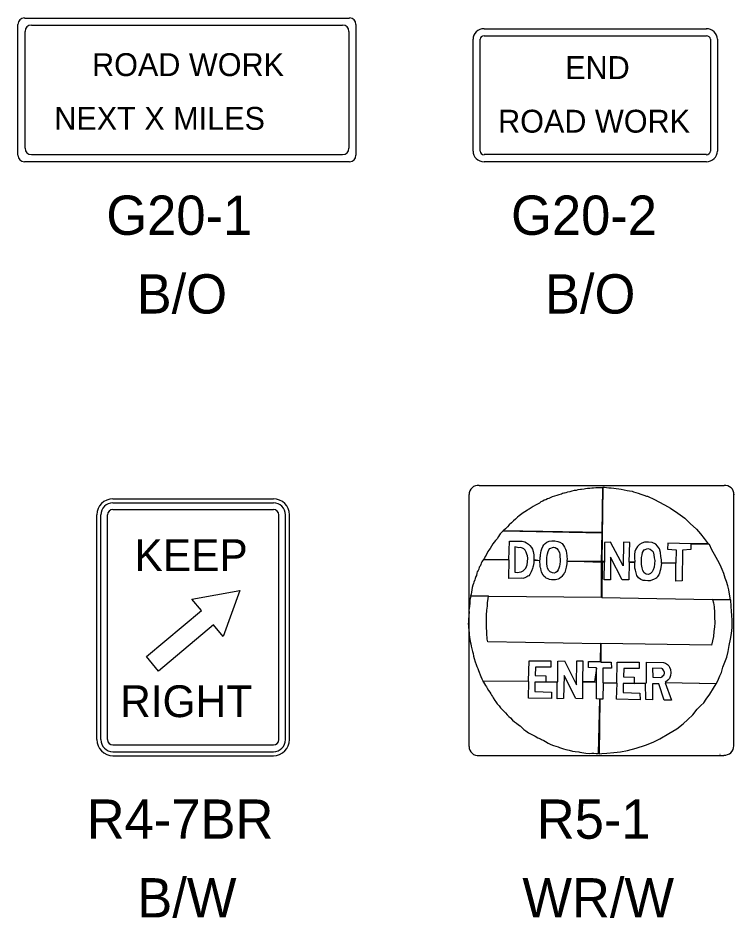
# Model space of a CAD drawing. Extents: x 10034 to 10794, y 10044 to 10499.
# Drawn here: x 10107 to 10170.8, y 10408.8 to 10488.9 of the extents above; entities that cross this region are included whole.
import ezdxf

# ---------------------------------------------------------------- set-up
doc = ezdxf.new("R2010")
doc.units = 0
for name, color, linetype in [('DSDate', 7, 'Continuous'), ('DSIndex', 7, 'Continuous'), ('DSText', 7, 'Continuous'), ('PlotBorder_dp', 7, 'Continuous')]:
    doc.layers.add(name, color=color, linetype=linetype)

msp = doc.modelspace()

# ---------------------------------------------------------------- linework, layer by layer
at = {"layer": 'DSDate'}
for p, q in [((10108.184, 10488.322), (10135.926, 10488.322)), ((10107.618, 10477.339), (10107.618, 10487.756)), ((10136.492, 10487.756), (10136.492, 10477.339)), ((10148.186, 10477.091), (10148.186, 10487.048)), ((10148.544, 10487.367), (10168.351, 10487.367)), ((10168.71, 10487.048), (10168.71, 10477.091)), ((10135.926, 10476.772), (10108.184, 10476.772)), ((10168.351, 10476.773), (10148.544, 10476.773))]:
    msp.add_line(p, q, dxfattribs=at)
for centre, start, end in [((10108.183, 10487.757), 90, 180), ((10135.924, 10487.757), 0, 90), ((10108.183, 10477.339), 180, 270), ((10135.924, 10477.339), 270, 0)]:
    msp.add_arc(centre, 0.566, start, end, dxfattribs=at)
for centre, major_axis, start_param, end_param in [((10148.543, 10487.049), (-0.359, 0), 4.712389, 6.283185), ((10168.35, 10487.049), (-0.359, 0), 3.141593, 4.712389), ((10148.543, 10477.091), (-0.359, 0), 0, 1.570796), ((10168.35, 10477.091), (0.359, 0), 4.712389, 6.283185)]:
    msp.add_ellipse(centre, major_axis=major_axis, ratio=0.888888, start_param=start_param, end_param=end_param, dxfattribs=at)
at = {"layer": 'DSIndex'}
for p, q in [((10148.104, 10447.307), (10169.927, 10447.307)), ((10147.212, 10424.055), (10147.212, 10446.487)), ((10170.801, 10424.11), (10170.801, 10446.578)), ((10115.457, 10446.119), (10129.76, 10446.119)), ((10115.457, 10445.761), (10129.76, 10445.761)), ((10114.025, 10424.662), (10114.025, 10444.689)), ((10114.382, 10424.662), (10114.382, 10444.689)), ((10114.98, 10424.662), (10114.98, 10444.689)), ((10115.457, 10445.166), (10129.76, 10445.166)), ((10130.238, 10424.662), (10130.238, 10444.689)), ((10130.832, 10424.662), (10130.832, 10444.689)), ((10131.191, 10424.662), (10131.191, 10444.689)), ((10115.457, 10424.185), (10129.76, 10424.185)), ((10115.457, 10423.589), (10129.76, 10423.589)), ((10115.457, 10423.23), (10129.76, 10423.23)), ((10148.104, 10423.235), (10169.908, 10423.235))]:
    msp.add_line(p, q, dxfattribs=at)
for points in [[(10159.069, 10443.097), (10159.126, 10447.137), (10159.079, 10447.096), (10158.97, 10447.09), (10158.831, 10447.096), (10158.634, 10447.092), (10158.492, 10447.082), (10158.282, 10447.067), (10158.153, 10447.063), (10157.965, 10447.04), (10157.863, 10447.022), (10157.759, 10447.022), (10157.574, 10447.006), (10157.451, 10446.98), (10157.231, 10446.946), (10157.134, 10446.938), (10156.925, 10446.911), (10156.908, 10446.912), (10156.755, 10446.867), (10156.556, 10446.844), (10156.361, 10446.798), (10156.176, 10446.751), (10155.968, 10446.695), (10155.816, 10446.661), (10155.702, 10446.628), (10155.638, 10446.612), (10155.522, 10446.58), (10155.44, 10446.527), (10155.191, 10446.46), (10155.018, 10446.418), (10154.816, 10446.348), (10154.619, 10446.277), (10154.316, 10446.141), (10154.204, 10446.11), (10154.034, 10446.025), (10153.9, 10445.982), (10153.767, 10445.914), (10153.61, 10445.837), (10153.483, 10445.739), (10153.294, 10445.644), (10153.11, 10445.547), (10152.919, 10445.427), (10152.722, 10445.312), (10152.547, 10445.192), (10152.47, 10445.161), (10152.4, 10445.108), (10152.185, 10444.958), (10152.029, 10444.854), (10151.892, 10444.772), (10151.662, 10444.59), (10151.505, 10444.49), (10151.352, 10444.309), (10151.159, 10444.163), (10151.131, 10444.129), (10150.984, 10443.971), (10150.784, 10443.792), (10150.62, 10443.612), (10150.434, 10443.43), (10150.251, 10443.274)], [(10159.154, 10447.151), (10159.265, 10447.151), (10159.447, 10447.126), (10159.665, 10447.096), (10159.858, 10447.087), (10160.093, 10447.063), (10160.309, 10447.043), (10160.563, 10447.015), (10160.773, 10446.974), (10161.027, 10446.915), (10161.284, 10446.868), (10161.494, 10446.813), (10161.742, 10446.783), (10161.858, 10446.728), (10162.064, 10446.687), (10162.288, 10446.608), (10162.517, 10446.539), (10162.775, 10446.45), (10163.016, 10446.345), (10163.096, 10446.337), (10163.743, 10446.049), (10164.127, 10445.852), (10164.614, 10445.58), (10165.15, 10445.28), (10165.823, 10444.834), (10166.419, 10444.393), (10166.913, 10443.921), (10167.476, 10443.396), (10167.827, 10442.999), (10168.143, 10442.588), (10168.518, 10442.095), (10167.003, 10442.097), (10164.913, 10442.153), (10164.895, 10441.621), (10165.657, 10441.564), (10165.644, 10440.383), (10164.366, 10440.376), (10164.359, 10440.671), (10164.297, 10440.973), (10164.256, 10441.324), (10164.162, 10441.652), (10163.993, 10441.887), (10163.835, 10442.068), (10163.516, 10442.221), (10163.207, 10442.265), (10162.838, 10442.246), (10162.6, 10442.169), (10162.384, 10442.046), (10162.226, 10441.876), (10162.08, 10441.641), (10161.99, 10441.419), (10161.961, 10441.147), (10161.96, 10440.896), (10161.982, 10440.471), (10161.485, 10440.477), (10161.525, 10442.217), (10160.962, 10442.238), (10160.934, 10440.145), (10159.814, 10442.258), (10159.276, 10442.217), (10159.279, 10440.461), (10159.065, 10440.472)], [(10159.014, 10440.47), (10159.074, 10443.111), (10150.237, 10443.257), (10150.125, 10443.137), (10149.977, 10442.994), (10149.907, 10442.904), (10149.821, 10442.748), (10149.698, 10442.56), (10149.571, 10442.413), (10149.436, 10442.244), (10149.327, 10442.097), (10149.196, 10441.891), (10149.074, 10441.677), (10148.959, 10441.544), (10148.878, 10441.43), (10148.732, 10441.105), (10148.646, 10440.971), (10148.566, 10440.838), (10148.474, 10440.699), (10150.739, 10440.668), (10150.811, 10442.343), (10151.934, 10442.338), (10152.16, 10442.291), (10152.316, 10442.205), (10152.506, 10442.078), (10152.626, 10441.969), (10152.778, 10441.768), (10152.858, 10441.632), (10152.912, 10441.433), (10152.949, 10441.28), (10152.979, 10441.118), (10152.967, 10440.949), (10152.986, 10440.813), (10152.976, 10440.614), (10153.509, 10440.641), (10153.537, 10440.694), (10153.537, 10440.793), (10153.552, 10440.913), (10153.565, 10441.02), (10153.576, 10441.138), (10153.608, 10441.299), (10153.627, 10441.473), (10153.687, 10441.669), (10153.769, 10441.853), (10153.87, 10442.003), (10153.987, 10442.13), (10154.143, 10442.252), (10154.353, 10442.34), (10154.577, 10442.363), (10154.844, 10442.359), (10155.109, 10442.315), (10155.286, 10442.247), (10155.489, 10442.143), (10155.614, 10441.969), (10155.718, 10441.803), (10155.807, 10441.632), (10155.852, 10441.467), (10155.884, 10441.255), (10155.91, 10441.075), (10155.921, 10440.914), (10155.931, 10440.801), (10155.914, 10440.586)], [(10151.291, 10441.83), (10151.293, 10439.577), (10151.508, 10439.563), (10151.667, 10439.582), (10151.85, 10439.624), (10152.018, 10439.691), (10152.136, 10439.819), (10152.252, 10439.948), (10152.367, 10440.235), (10152.407, 10440.514), (10152.424, 10440.827), (10152.405, 10441.023), (10152.336, 10441.194), (10152.303, 10441.351), (10152.191, 10441.547), (10152.068, 10441.647), (10151.96, 10441.724), (10151.798, 10441.77), (10151.627, 10441.759)], [(10154.734, 10441.811), (10154.883, 10441.783), (10155.014, 10441.69), (10155.15, 10441.548), (10155.247, 10441.334), (10155.282, 10441.16), (10155.305, 10440.94), (10155.308, 10440.751), (10155.308, 10440.532), (10155.285, 10440.304), (10155.251, 10440.128), (10155.214, 10439.95), (10155.145, 10439.801), (10155.047, 10439.642), (10154.928, 10439.543), (10154.785, 10439.494), (10154.637, 10439.508), (10154.432, 10439.604), (10154.301, 10439.736), (10154.204, 10439.933), (10154.157, 10440.121), (10154.136, 10440.323), (10154.124, 10440.511), (10154.127, 10440.692), (10154.135, 10440.881), (10154.158, 10441.066), (10154.191, 10441.221), (10154.255, 10441.41), (10154.32, 10441.575), (10154.414, 10441.687)], [(10168.62, 10442.046), (10166.963, 10442.081), (10166.969, 10441.588), (10166.233, 10441.554), (10166.193, 10438.806), (10165.625, 10438.792), (10165.631, 10440.363), (10164.342, 10440.373), (10164.334, 10440.172), (10164.286, 10440.031), (10164.258, 10439.821), (10164.217, 10439.631), (10164.17, 10439.502), (10164.102, 10439.331), (10163.989, 10439.203), (10163.934, 10439.089), (10163.839, 10439.025), (10163.709, 10438.944), (10163.33, 10438.814), (10163.135, 10438.8), (10162.908, 10438.834), (10162.725, 10438.848), (10162.519, 10438.921), (10162.301, 10439.08), (10162.159, 10439.288), (10162.091, 10439.509), (10162.023, 10439.747), (10161.982, 10439.94), (10161.966, 10440.201), (10161.981, 10440.437), (10161.474, 10440.429), (10161.448, 10438.894), (10160.857, 10438.908), (10159.806, 10440.92), (10159.799, 10438.892), (10159.236, 10438.891), (10159.271, 10440.518), (10159.061, 10440.521), (10159.032, 10437.309), (10170.501, 10437.117), (10170.413, 10437.617), (10170.35, 10438.015), (10170.252, 10438.366), (10170.137, 10438.746), (10170.039, 10439.045), (10169.905, 10439.447), (10169.769, 10439.828), (10169.578, 10440.226), (10169.372, 10440.626), (10169.08, 10441.146), (10168.853, 10441.578)], [(10163.138, 10441.696), (10163.341, 10441.64), (10163.498, 10441.513), (10163.62, 10441.391), (10163.683, 10441.126), (10163.693, 10440.865), (10163.757, 10440.614), (10163.744, 10440.309), (10163.697, 10440.017), (10163.615, 10439.802), (10163.532, 10439.614), (10163.367, 10439.467), (10163.193, 10439.374), (10162.983, 10439.413), (10162.819, 10439.524), (10162.69, 10439.724), (10162.625, 10439.954), (10162.568, 10440.277), (10162.562, 10440.572), (10162.568, 10440.874), (10162.634, 10441.119), (10162.67, 10441.336), (10162.741, 10441.491), (10162.82, 10441.581)], [(10159.016, 10437.349), (10159.016, 10440.527), (10155.92, 10440.532), (10155.903, 10440.316), (10155.889, 10440.172), (10155.853, 10440.038), (10155.838, 10439.916), (10155.801, 10439.8), (10155.774, 10439.666), (10155.723, 10439.55), (10155.659, 10439.447), (10155.605, 10439.343), (10155.542, 10439.279), (10155.483, 10439.188), (10155.407, 10439.122), (10155.262, 10439.026), (10155.128, 10438.965), (10155.037, 10438.922), (10154.919, 10438.908), (10154.725, 10438.885), (10154.561, 10438.889), (10154.373, 10438.937), (10154.25, 10438.972), (10154.07, 10439.055), (10153.97, 10439.133), (10153.863, 10439.227), (10153.791, 10439.342), (10153.725, 10439.452), (10153.654, 10439.598), (10153.619, 10439.727), (10153.585, 10439.894), (10153.571, 10439.97), (10153.544, 10440.081), (10153.532, 10440.2), (10153.533, 10440.312), (10153.516, 10440.432), (10153.501, 10440.595), (10152.989, 10440.678), (10152.981, 10440.543), (10152.959, 10440.424), (10152.945, 10440.254), (10152.921, 10440.126), (10152.893, 10440.019), (10152.858, 10439.907), (10152.824, 10439.821), (10152.799, 10439.755), (10152.744, 10439.608), (10152.675, 10439.478), (10152.62, 10439.38), (10152.525, 10439.257), (10152.438, 10439.209), (10152.348, 10439.162), (10152.232, 10439.091), (10152.174, 10439.077), (10152.083, 10439.043), (10151.994, 10439.028), (10151.908, 10439.034), (10150.745, 10439.016), (10150.785, 10440.668), (10148.487, 10440.708), (10148.412, 10440.595), (10148.346, 10440.493), (10148.288, 10440.383), (10148.245, 10440.264), (10148.177, 10440.124), (10148.114, 10440.018), (10148.073, 10439.847), (10148.022, 10439.74), (10147.935, 10439.601), (10147.907, 10439.499), (10147.849, 10439.27), (10147.802, 10439.193), (10147.742, 10439.028), (10147.716, 10438.909), (10147.636, 10438.695), (10147.587, 10438.57), (10147.537, 10438.408), (10147.485, 10438.202), (10147.449, 10438.007), (10147.415, 10437.793), (10147.374, 10437.635), (10147.333, 10437.483), (10148.971, 10437.456)], [(10119.527, 10430.763), (10118.438, 10432.059), (10123.345, 10436.158), (10122.48, 10437.187), (10126.768, 10437.945), (10125.278, 10433.854), (10124.413, 10434.884)], [(10148.945, 10437.442), (10147.344, 10437.456), (10147.299, 10437.243), (10147.278, 10437.048), (10147.255, 10436.779), (10147.226, 10436.564), (10147.221, 10436.308), (10147.186, 10436.224), (10147.196, 10435.967), (10147.173, 10435.805), (10147.166, 10435.623), (10147.15, 10435.438), (10147.143, 10435.341), (10147.14, 10435.12), (10147.13, 10434.974), (10147.147, 10434.793), (10147.145, 10434.602), (10147.177, 10434.479), (10147.184, 10434.377), (10147.197, 10434.176), (10147.22, 10433.992), (10147.244, 10433.789), (10147.259, 10433.596), (10147.288, 10433.454), (10147.293, 10433.402), (10147.355, 10433.188), (10147.402, 10432.999), (10147.456, 10432.748), (10147.5, 10432.518), (10147.551, 10432.328), (10147.606, 10432.091), (10147.669, 10431.885), (10147.748, 10431.584), (10147.825, 10431.347), (10147.903, 10431.173), (10147.975, 10430.984), (10148.046, 10430.826), (10148.095, 10430.685), (10148.188, 10430.423), (10148.244, 10430.3), (10148.347, 10430.079), (10148.408, 10429.962), (10148.426, 10429.894), (10152.502, 10429.883), (10152.565, 10431.677), (10154.484, 10431.683), (10154.49, 10431.104), (10153.108, 10431.109), (10153.098, 10430.363), (10154.034, 10430.342), (10154.034, 10429.814), (10155.118, 10429.805), (10155.101, 10431.652), (10155.693, 10431.696), (10156.777, 10429.536), (10156.798, 10431.682), (10157.349, 10431.674), (10157.317, 10429.807), (10158.556, 10429.794), (10158.546, 10431.064), (10157.861, 10431.099), (10157.856, 10431.612), (10158.905, 10431.609), (10158.934, 10433.189), (10148.886, 10433.365), (10148.844, 10433.501), (10148.823, 10433.604), (10148.827, 10433.68), (10148.817, 10433.82), (10148.793, 10433.943), (10148.793, 10434.026), (10148.788, 10434.129), (10148.788, 10434.211), (10148.777, 10434.386), (10148.759, 10434.521), (10148.752, 10434.713), (10148.746, 10434.944), (10148.743, 10435.121), (10148.745, 10435.351), (10148.742, 10435.499), (10148.762, 10435.665), (10148.761, 10435.902), (10148.775, 10436.042), (10148.79, 10436.181), (10148.807, 10436.364), (10148.834, 10436.552), (10148.838, 10436.755), (10148.854, 10436.885), (10148.886, 10437.028)], [(10170.54, 10437.107), (10168.911, 10437.141), (10168.981, 10436.842), (10169.041, 10436.49), (10169.064, 10435.986), (10169.074, 10435.581), (10169.097, 10435.071), (10169.073, 10434.711), (10169.03, 10434.308), (10168.992, 10433.86), (10168.898, 10433.475), (10168.812, 10433.063), (10158.958, 10433.219), (10158.943, 10431.564), (10159.878, 10431.563), (10159.884, 10431.042), (10159.124, 10431.015), (10159.131, 10429.722), (10160.373, 10429.736), (10160.405, 10431.552), (10162.365, 10431.564), (10162.354, 10430.99), (10160.993, 10430.988), (10160.977, 10430.261), (10161.912, 10430.218), (10161.912, 10429.67), (10163.008, 10429.711), (10163.013, 10431.558), (10164.531, 10431.54), (10164.713, 10431.472), (10164.891, 10431.35), (10164.993, 10431.226), (10165.081, 10431.106), (10165.148, 10430.907), (10165.18, 10430.62), (10165.144, 10430.377), (10165.065, 10430.105), (10164.922, 10429.96), (10164.693, 10429.747), (10169.27, 10429.656), (10169.42, 10430.046), (10169.557, 10430.345), (10169.688, 10430.643), (10169.825, 10431.118), (10170.006, 10431.55), (10170.17, 10431.999), (10170.299, 10432.509), (10170.399, 10433.051), (10170.514, 10433.611), (10170.59, 10434.109), (10170.647, 10434.662), (10170.639, 10435.084), (10170.667, 10435.316), (10170.637, 10435.717), (10170.596, 10436.111), (10170.571, 10436.536)], [(10152.538, 10429.842), (10148.427, 10429.876), (10148.48, 10429.77), (10148.59, 10429.634), (10148.657, 10429.479), (10148.759, 10429.358), (10148.825, 10429.257), (10148.94, 10429.045), (10149.042, 10428.893), (10149.127, 10428.751), (10149.21, 10428.61), (10149.296, 10428.496), (10149.358, 10428.372), (10149.486, 10428.157), (10149.581, 10428.035), (10149.717, 10427.861), (10149.873, 10427.661), (10150.002, 10427.498), (10150.098, 10427.409), (10150.283, 10427.236), (10150.438, 10427.05), (10150.589, 10426.883), (10150.75, 10426.722), (10150.896, 10426.595), (10151.079, 10426.393), (10151.246, 10426.254), (10151.429, 10426.119), (10151.62, 10425.988), (10151.766, 10425.895), (10151.909, 10425.757), (10152.093, 10425.576), (10152.258, 10425.453), (10152.507, 10425.262), (10152.722, 10425.137), (10152.901, 10425.072), (10153.093, 10424.962), (10153.334, 10424.826), (10153.559, 10424.72), (10153.659, 10424.671), (10153.858, 10424.584), (10154.025, 10424.493), (10154.244, 10424.359), (10154.498, 10424.237), (10154.722, 10424.151), (10154.931, 10424.087), (10155.129, 10424.019), (10155.268, 10423.963), (10155.357, 10423.942), (10155.608, 10423.834), (10155.833, 10423.779), (10156.119, 10423.716), (10156.424, 10423.643), (10156.665, 10423.612), (10156.981, 10423.576), (10157.077, 10423.542), (10157.267, 10423.514), (10157.594, 10423.449), (10157.973, 10423.428), (10158.158, 10423.458), (10158.326, 10423.445), (10158.515, 10423.432), (10158.741, 10423.413), (10158.846, 10428.277), (10158.55, 10428.305), (10158.565, 10431.036), (10158.381, 10429.808), (10158.192, 10429.813), (10157.947, 10429.815), (10157.751, 10429.813), (10157.55, 10429.814), (10157.365, 10429.813), (10157.317, 10429.82), (10157.31, 10428.292), (10156.715, 10428.312), (10155.683, 10430.376), (10155.629, 10428.311), (10155.052, 10428.302), (10155.068, 10429.752), (10153.991, 10429.781), (10153.056, 10429.78), (10153.069, 10428.936), (10154.541, 10428.889), (10154.547, 10428.318), (10152.5, 10428.352)], [(10163.563, 10431.033), (10163.572, 10430.233), (10164.294, 10430.205), (10164.403, 10430.266), (10164.485, 10430.337), (10164.549, 10430.397), (10164.59, 10430.48), (10164.625, 10430.566), (10164.613, 10430.636), (10164.605, 10430.731), (10164.563, 10430.797), (10164.507, 10430.888), (10164.443, 10430.955), (10164.373, 10431.003)], [(10169.232, 10429.638), (10164.681, 10429.726), (10165.244, 10428.183), (10164.596, 10428.187), (10164.106, 10429.618), (10163.563, 10429.63), (10163.558, 10428.216), (10162.956, 10428.241), (10162.936, 10429.663), (10160.947, 10429.672), (10160.947, 10428.864), (10162.415, 10428.805), (10162.44, 10428.195), (10160.353, 10428.268), (10160.413, 10429.698), (10159.147, 10429.733), (10159.115, 10428.276), (10158.866, 10428.266), (10158.783, 10423.385), (10159.027, 10423.42), (10159.468, 10423.458), (10160.1, 10423.516), (10160.703, 10423.571), (10161.332, 10423.699), (10162.093, 10423.888), (10162.913, 10424.168), (10163.612, 10424.433), (10164.197, 10424.743), (10165.02, 10425.195), (10165.719, 10425.62), (10166.278, 10426.064), (10166.71, 10426.444), (10167.148, 10426.862), (10167.546, 10427.366), (10167.85, 10427.715), (10168.116, 10427.943), (10168.344, 10428.266), (10168.648, 10428.718), (10168.98, 10429.247)]]:
    msp.add_lwpolyline(points, close=True, dxfattribs=at)
for centre, radius, start, end in [((10148.01, 10446.513), 0.8, 83.33482, 181.83716), ((10170.018, 10446.501), 0.8, 358.16284, 96.66518), ((10115.454, 10444.689), 1.43, 90, 180), ((10115.454, 10444.689), 1.073, 90, 180), ((10129.759, 10444.689), 1.43, 0, 90), ((10129.759, 10444.689), 1.073, 0, 90), ((10115.454, 10444.689), 0.477, 90, 180), ((10129.759, 10444.689), 0.477, 0, 90), ((10115.454, 10424.662), 1.43, 180, 270), ((10115.454, 10424.662), 1.073, 180, 270), ((10115.454, 10424.662), 0.477, 180, 270), ((10129.759, 10424.662), 1.43, 270, 0), ((10129.759, 10424.662), 1.073, 270, 0), ((10129.759, 10424.662), 0.477, 270, 0), ((10148.01, 10424.03), 0.8, 178.16284, 276.66518), ((10169.999, 10424.085), 0.8, 263.33482, 1.83716), ((10169.954, 10424.059), 0.795, 9.81495, 10.98253), ((10169.954, 10424.059), 0.795, 240.06314, 241.84381)]:
    msp.add_arc(centre, radius, start, end, dxfattribs=at)
at = {"layer": 'DSText'}
for p, q in [((10107.559, 10488.947), (10136.551, 10488.947)), ((10106.992, 10476.714), (10106.992, 10488.381)), ((10137.117, 10488.381), (10137.117, 10476.714)), ((10148.544, 10487.992), (10168.351, 10487.992)), ((10147.56, 10477.091), (10147.56, 10487.048)), ((10169.335, 10487.048), (10169.335, 10477.091)), ((10136.551, 10476.147), (10107.559, 10476.147)), ((10168.351, 10476.148), (10148.544, 10476.148))]:
    msp.add_line(p, q, dxfattribs=at)
for centre, start, end in [((10107.557, 10488.382), 90, 180), ((10136.549, 10488.382), 0, 90), ((10107.557, 10476.714), 180, 270), ((10136.549, 10476.714), 270, 0)]:
    msp.add_arc(centre, 0.566, start, end, dxfattribs=at)
for centre, major_axis, start_param, end_param in [((10148.543, 10487.049), (-0.984, 0), 4.712389, 6.283185), ((10168.35, 10487.049), (-0.984, 0), 3.141593, 4.712389), ((10148.543, 10477.091), (-0.984, 0), 0, 1.570796), ((10168.35, 10477.091), (0.984, 0), 4.712389, 6.283185)]:
    msp.add_ellipse(centre, major_axis=major_axis, ratio=0.959484, start_param=start_param, end_param=end_param, dxfattribs=at)

# ---------------------------------------------------------------- texts
at = {"layer": 'DSIndex'}
for s, height, p in [('KEEP', 2.8308, (10117.37, 10439.681)), ('RIGHT', 2.8308, (10116.095, 10426.667)), ('R4-7BR', 3.5, (10113.116, 10415.832)), ('R5-1', 3.5, (10153.239, 10415.832)), ('B/W', 3.5, (10117.626, 10408.821)), ('WR/W', 3.5, (10151.954, 10408.821))]:
    msp.add_text(s, height=height, dxfattribs=at).set_placement(p)
at = {"layer": 'PlotBorder_dp'}
for s, height, p in [('ROAD WORK', 2.0382, (10113.594, 10483.775)), ('END', 2.0382, (10155.768, 10483.51)), ('NEXT X MILES', 2.03818, (10110.224, 10478.986)), ('ROAD WORK', 2.0382, (10149.788, 10478.734)), ('G20-1', 3.5, (10114.866, 10469.63)), ('G20-2', 3.5, (10150.944, 10469.63)), ('B/O', 3.5, (10117.569, 10462.619)), ('B/O', 3.5, (10153.963, 10462.619))]:
    msp.add_text(s, height=height, dxfattribs=at).set_placement(p)

doc.saveas('drawing.dxf')
